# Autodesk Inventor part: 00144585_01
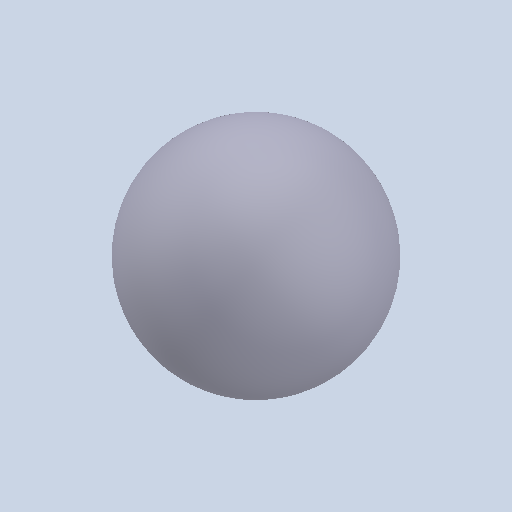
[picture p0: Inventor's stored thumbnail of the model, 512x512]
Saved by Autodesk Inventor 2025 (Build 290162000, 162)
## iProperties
Created: 2021-02
Part Number: 00144585_01
Material: Generico
Document SubType Name: Modeling
Designer: Ryzen5700u
Density: 1 g/cm^3
Appearance: Default
Author: Ryzen5700u
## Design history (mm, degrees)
feature "Solido1"
node "Solido2"
